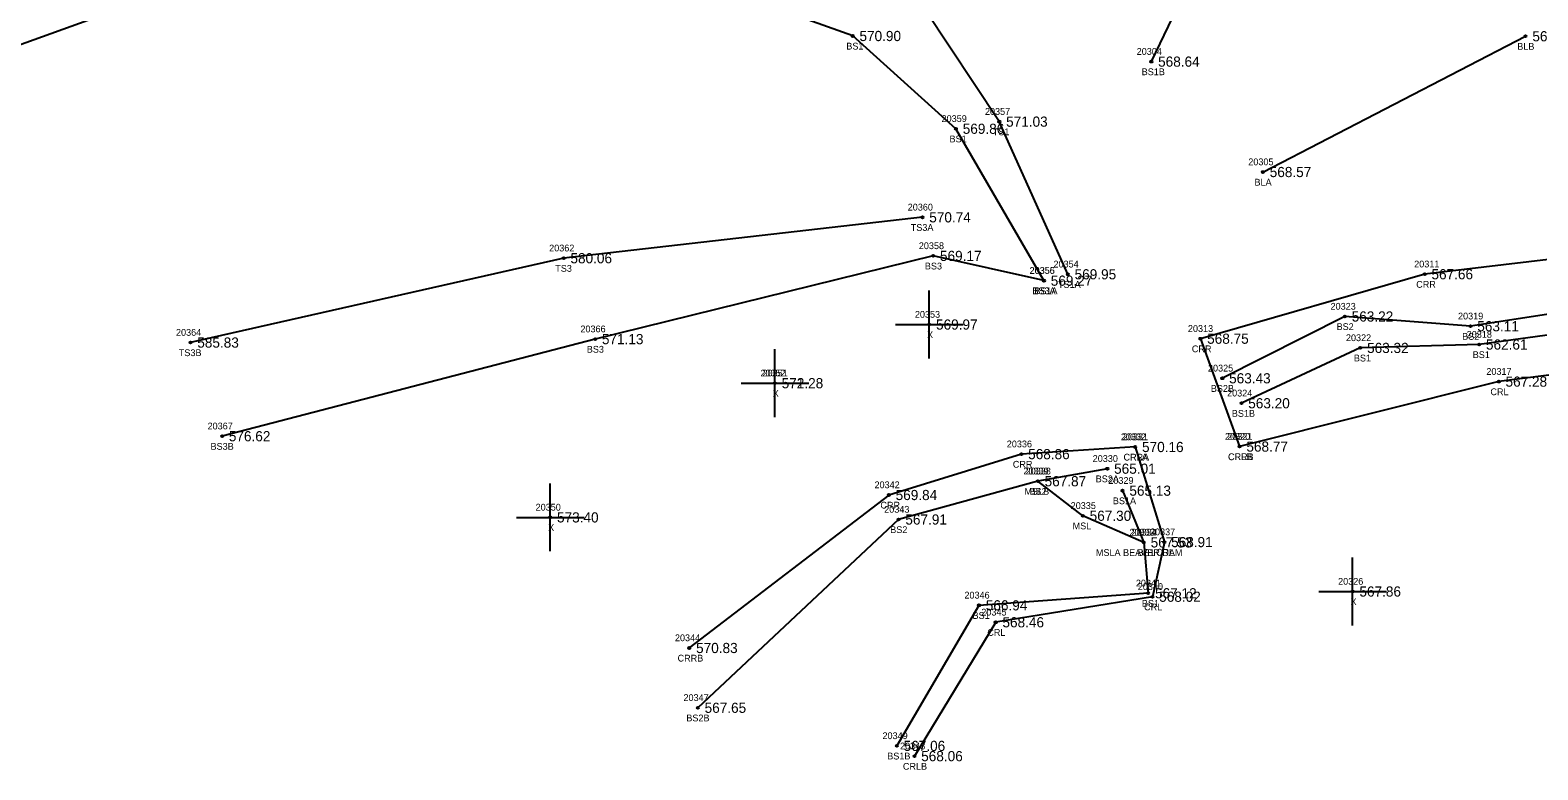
# Model space of a CAD drawing. Extents: x 1530159 to 1531652, y 877045 to 877724.
# Drawn here: x 1530693.4 to 1530915.9, y 877122.4 to 877231.5 of the extents above; entities that cross this region are included whole.
import ezdxf

# ---------------------------------------------------------------- set-up
doc = ezdxf.new("R2010")
doc.units = 0
for name, color, linetype in [('RD_DTM_BkLn1', 7, 'Continuous'), ('RD_DTM_BkLn2', 7, 'Continuous'), ('RD_DTM_BkLn_txCode', 7, 'Continuous'), ('RD_EX_H2O', 7, 'Continuous'), ('RD_EX_H2O_txCode', 7, 'Continuous'), ('RD_EX_Misc', 7, 'Continuous'), ('RD_EX_Misc_txCode', 7, 'Continuous'), ('RD_EX_TX_H2O_ELEV', 7, 'Continuous'), ('RD_EX_TX_Misc_ELEV', 7, 'Continuous'), ('RD_SMD_Locator', 7, 'Continuous')]:
    doc.layers.add(name, color=color, linetype=linetype)

msp = doc.modelspace()

# ---------------------------------------------------------------- linework, layer by layer
at = {"layer": 'RD_DTM_BkLn1'}
msp.add_line((1530875.34, 877210.59), (1530914.1, 877230.61), dxfattribs=at)
at = {"layer": 'RD_DTM_BkLn2'}
for points in [[(1530846.55, 877195.51), (1530836.44, 877218.02), (1530825.43, 877234.54), (1530809.73, 877254.08), (1530787.3, 877254.89), (1530761.32, 877254.01), (1530707.75, 877254.4), (1530659.82, 877254.09), (1530608.22, 877255.41), (1530556.36, 877261.96), (1530505.86, 877268.16), (1530455.53, 877277.54), (1530404.07, 877287.69), (1530355.59, 877301.63), (1530305.18, 877312.26), (1530242.86, 877334.32), (1530183.05, 877357.3)], [(1530843.03, 877194.57), (1530830.04, 877216.97), (1530814.8, 877230.65), (1530802.93, 877234.88), (1530787.62, 877244.18), (1530761.15, 877248.01), (1530710.15, 877249.2), (1530659.29, 877248.38), (1530607.91, 877252.81), (1530555.6, 877260.07), (1530504.64, 877266.43), (1530454.3, 877275.47), (1530403.13, 877286.43), (1530354.95, 877299.51), (1530304.97, 877310.18), (1530241.94, 877332.54), (1530182.43, 877355.46)], [(1530781.59, 877237.74), (1530769.19, 877234.54), (1530707.91, 877235.08), (1530658.9, 877217.43), (1530601.44, 877222.78), (1530585.47, 877250.74), (1530554.71, 877252.85), (1530502.71, 877258.91), (1530451.66, 877269.63), (1530401.38, 877279.82), (1530344.51, 877291.95), (1530339.77, 877285.8), (1530357.81, 877267.08), (1530377.75, 877244.03)], [(1530880.22, 877248.53), (1530867.02, 877243.9), (1530858.87, 877226.87)], [(1530825.1, 877203.91), (1530772.15, 877197.88), (1530717.08, 877185.44)], [(1530843.03, 877194.57), (1530826.68, 877198.22), (1530776.79, 877185.95), (1530721.74, 877171.63)], [(1530978.51, 877193.14), (1530965.87, 877197.06), (1530905.97, 877187.85), (1530887.44, 877189.29), (1530869.35, 877180.17)], [(1530993.41, 877183.7), (1530965.37, 877193.1), (1530907.25, 877185.15), (1530889.71, 877184.65), (1530872.17, 877176.49)], [(1530852.38, 877166.84), (1530842.12, 877164.99), (1530821.57, 877159.35), (1530791.95, 877131.58)], [(1530854.63, 877163.6), (1530857.77, 877155.97), (1530858.42, 877148.47), (1530833.44, 877146.69), (1530821.32, 877125.96)], [(1530857.77, 877155.97), (1530848.77, 877159.9), (1530842.12, 877164.99)]]:
    msp.add_lwpolyline(points, dxfattribs=at)
at = {"layer": 'RD_EX_H2O'}
for points in [[(1530972.1, 877196.48), (1530956.06, 877202.24), (1530899.21, 877195.52), (1530866.11, 877186.01), (1530871.9, 877170.1)], [(1530991.55, 877179.5), (1530965.66, 877186.74), (1530910.14, 877179.68), (1530871.9, 877170.1)], [(1530856.5, 877170.04), (1530839.69, 877168.99), (1530820.14, 877162.96), (1530790.69, 877140.4)], [(1530856.5, 877170.04), (1530860.79, 877156.02), (1530859.03, 877147.96), (1530835.9, 877144.19), (1530823.91, 877124.45)]]:
    msp.add_lwpolyline(points, dxfattribs=at)
at = {"layer": 'RD_EX_Misc'}
for p, q in [((1530826.1, 877183.1), (1530826.1, 877193.1)), ((1530821.1, 877188.1), (1530831.1, 877188.1)), ((1530803.32, 877174.45), (1530803.32, 877184.45)), ((1530803.32, 877174.45), (1530803.32, 877184.45)), ((1530798.32, 877179.45), (1530808.32, 877179.45)), ((1530798.32, 877179.45), (1530808.32, 877179.45)), ((1530770.17, 877154.66), (1530770.17, 877164.66)), ((1530765.17, 877159.66), (1530775.17, 877159.66)), ((1530888.58, 877143.73), (1530888.58, 877153.73)), ((1530883.58, 877148.73), (1530893.58, 877148.73))]:
    msp.add_line(p, q, dxfattribs=at)
at = {"layer": 'RD_SMD_Locator'}
for centre in [(1530814.8, 877230.65), (1530914.1, 877230.61), (1530858.87, 877226.87), (1530830.04, 877216.97), (1530836.44, 877218.02), (1530875.34, 877210.59), (1530825.1, 877203.91), (1530772.15, 877197.88), (1530826.68, 877198.22), (1530843.03, 877194.57), (1530843.03, 877194.57), (1530846.55, 877195.51), (1530899.21, 877195.52), (1530826.1, 877188.1), (1530887.44, 877189.29), (1530905.97, 877187.85), (1530717.08, 877185.44), (1530776.79, 877185.95), (1530866.11, 877186.01), (1530907.25, 877185.15), (1530889.71, 877184.65), (1530803.32, 877179.45), (1530803.32, 877179.45), (1530869.35, 877180.17), (1530910.14, 877179.68), (1530872.17, 877176.49), (1530721.74, 877171.63), (1530856.5, 877170.04), (1530856.5, 877170.04), (1530871.9, 877170.1), (1530871.9, 877170.1), (1530839.69, 877168.99), (1530842.12, 877164.99), (1530842.12, 877164.99), (1530852.38, 877166.84), (1530820.14, 877162.96), (1530854.63, 877163.6), (1530770.17, 877159.66), (1530821.57, 877159.35), (1530848.77, 877159.9), (1530857.77, 877155.97), (1530857.77, 877155.97), (1530860.79, 877156.02), (1530858.42, 877148.47), (1530859.03, 877147.96), (1530888.58, 877148.73), (1530833.44, 877146.69), (1530835.9, 877144.19), (1530790.69, 877140.4), (1530791.95, 877131.58), (1530821.32, 877125.96), (1530823.91, 877124.45)]:
    msp.add_circle(centre, 0.15, dxfattribs=at)

# ---------------------------------------------------------------- texts
at = {"layer": 'RD_DTM_BkLn_txCode'}
for s, p in [('BS1', (1530813.86, 877228.65)), ('BLB', (1530912.87, 877228.61)), ('20304', (1530856.71, 877227.87)), ('BS1B', (1530857.45, 877224.87)), ('20359', (1530827.92, 877217.97)), ('20357', (1530834.32, 877219.02)), ('TS1', (1530835.48, 877216.02)), ('BS1', (1530829.09, 877214.97)), ('20305', (1530873.18, 877211.59)), ('BLA', (1530874.09, 877208.59)), ('20360', (1530822.92, 877204.91)), ('TS3A', (1530823.37, 877201.91)), ('20362', (1530770.01, 877198.88)), ('20358', (1530824.56, 877199.22)), ('TS3', (1530770.91, 877195.88)), ('BS3', (1530825.45, 877196.22)), ('20356', (1530840.89, 877195.57)), ('20355', (1530840.92, 877195.57)), ('20354', (1530844.43, 877196.51)), ('TS1A', (1530845.1, 877193.51)), ('BS3A', (1530841.32, 877192.57)), ('BS1A', (1530841.6, 877192.57)), ('20323', (1530885.32, 877190.29)), ('20319', (1530904.13, 877188.85)), ('20364', (1530714.94, 877186.44)), ('20366', (1530774.62, 877186.95)), ('BS2', (1530886.21, 877187.29)), ('20322', (1530887.59, 877185.65)), ('BS2', (1530904.74, 877185.85)), ('20318', (1530905.41, 877186.15)), ('TS3B', (1530715.36, 877183.44)), ('BS3', (1530775.56, 877183.95)), ('BS1', (1530888.76, 877182.65)), ('BS1', (1530906.3, 877183.15)), ('20325', (1530867.23, 877181.17)), ('BS2B', (1530867.65, 877178.17)), ('20324', (1530870.05, 877177.49)), ('BS1B', (1530870.75, 877174.49)), ('20367', (1530719.6, 877172.63)), ('BS3B', (1530720.04, 877169.63)), ('20330', (1530850.22, 877167.84)), ('20339', (1530840, 877165.99)), ('BS2A', (1530850.66, 877164.84)), ('20329', (1530852.52, 877164.6)), ('BS2', (1530840.89, 877162.99)), ('20343', (1530819.45, 877160.35)), ('BS1A', (1530853.2, 877161.6)), ('BS2', (1530820.34, 877157.35)), ('20333', (1530855.65, 877156.97)), ('BS1', (1530856.82, 877153.97)), ('20341', (1530856.59, 877149.47)), ('20346', (1530831.29, 877147.69)), ('BS1', (1530857.48, 877146.47)), ('BS1', (1530832.49, 877144.69)), ('20347', (1530789.83, 877132.58)), ('BS2B', (1530790.25, 877129.58)), ('20349', (1530819.2, 877126.96)), ('BS1B', (1530819.9, 877123.96))]:
    msp.add_text(s, height=1, dxfattribs=at).set_placement(p)
at = {"layer": 'RD_EX_H2O_txCode'}
for s, p in [('20311', (1530897.66, 877196.52)), ('CRR', (1530897.96, 877193.52)), ('20313', (1530864.27, 877187.01)), ('CRR', (1530864.85, 877184.01)), ('20317', (1530908.31, 877180.68)), ('CRL', (1530908.91, 877177.68)), ('20332', (1530854.38, 877171.04)), ('20331', (1530854.66, 877171.04)), ('20320', (1530869.74, 877171.1)), ('20321', (1530870.07, 877171.1)), ('20336', (1530837.54, 877169.99)), ('CRR', (1530838.43, 877166.99)), ('CRRA', (1530854.76, 877168.04)), ('CRLA', (1530854.78, 877168.04)), ('CRRB', (1530870.18, 877168.1)), ('CRLB', (1530870.2, 877168.1)), ('20342', (1530818.02, 877163.96)), ('CRR', (1530818.89, 877160.96)), ('20337', (1530858.67, 877157.02)), ('CRL', (1530859.56, 877154.02)), ('20340', (1530856.87, 877148.96)), ('20345', (1530833.78, 877145.19)), ('CRL', (1530857.8, 877145.96)), ('CRL', (1530834.67, 877142.19)), ('20344', (1530788.57, 877141.4)), ('CRRB', (1530788.96, 877138.4)), ('20348', (1530821.79, 877125.45)), ('CRLB', (1530822.21, 877122.45))]:
    msp.add_text(s, height=1, dxfattribs=at).set_placement(p)
at = {"layer": 'RD_EX_Misc_txCode'}
for s, p in [('20353', (1530823.98, 877189.1)), ('X', (1530825.78, 877186.1)), ('20352', (1530801.2, 877180.45)), ('20351', (1530801.48, 877180.45)), ('X', (1530803, 877177.45)), ('X', (1530803, 877177.45)), ('20338', (1530840.32, 877165.99)), ('MSLB', (1530840.15, 877162.99)), ('20350', (1530768.01, 877160.66)), ('20335', (1530846.97, 877160.9)), ('X', (1530769.86, 877157.66)), ('MSL', (1530847.26, 877157.9)), ('20334', (1530855.94, 877156.97)), ('MSLA BEAVER DAM', (1530850.69, 877153.97)), ('20326', (1530886.43, 877149.73)), ('X', (1530888.26, 877146.73))]:
    msp.add_text(s, height=1, dxfattribs=at).set_placement(p)
at = {"layer": 'RD_EX_TX_H2O_ELEV'}
for s, p in [('567.66', (1530900.21, 877194.77)), ('568.75', (1530867.11, 877185.26)), ('567.28', (1530911.14, 877178.93)), ('568.86', (1530840.69, 877168.24)), ('570.16', (1530857.5, 877169.29)), ('570.16', (1530857.5, 877169.29)), ('568.77', (1530872.9, 877169.35)), ('568.77', (1530872.9, 877169.35)), ('569.84', (1530821.14, 877162.21)), ('568.91', (1530861.79, 877155.27)), ('568.02', (1530860.03, 877147.21)), ('568.46', (1530836.9, 877143.44)), ('570.83', (1530791.69, 877139.65)), ('568.06', (1530824.91, 877123.7))]:
    msp.add_text(s, height=1.5, dxfattribs=at).set_placement(p)
at = {"layer": 'RD_EX_TX_Misc_ELEV'}
for s, p in [('570.90', (1530815.8, 877229.9)), ('566.78', (1530915.1, 877229.86)), ('568.64', (1530859.87, 877226.12)), ('571.03', (1530837.44, 877217.27)), ('569.86', (1530831.04, 877216.22)), ('568.57', (1530876.34, 877209.84)), ('570.74', (1530826.1, 877203.16)), ('580.06', (1530773.15, 877197.13)), ('569.17', (1530827.68, 877197.47)), ('569.95', (1530847.55, 877194.76)), ('569.27', (1530844.03, 877193.82)), ('569.27', (1530844.03, 877193.82)), ('563.22', (1530888.44, 877188.54)), ('569.97', (1530827.1, 877187.35)), ('563.11', (1530906.97, 877187.1)), ('585.83', (1530718.08, 877184.69)), ('571.13', (1530777.79, 877185.2)), ('563.32', (1530890.71, 877183.9)), ('562.61', (1530908.25, 877184.4)), ('563.43', (1530870.35, 877179.42)), ('572.28', (1530804.32, 877178.7)), ('571.28', (1530804.32, 877178.7)), ('563.20', (1530873.17, 877175.74)), ('576.62', (1530722.74, 877170.88)), ('565.01', (1530853.38, 877166.09)), ('567.87', (1530843.12, 877164.24)), ('567.87', (1530843.12, 877164.24)), ('565.13', (1530855.63, 877162.85)), ('567.30', (1530849.77, 877159.15)), ('573.40', (1530771.17, 877158.91)), ('567.91', (1530822.57, 877158.6)), ('567.53', (1530858.77, 877155.22)), ('567.53', (1530858.77, 877155.22)), ('567.86', (1530889.58, 877147.98)), ('566.94', (1530834.44, 877145.94)), ('567.12', (1530859.42, 877147.72)), ('567.65', (1530792.95, 877130.83)), ('567.06', (1530822.32, 877125.21))]:
    msp.add_text(s, height=1.5, dxfattribs=at).set_placement(p)

doc.saveas('drawing.dxf')
